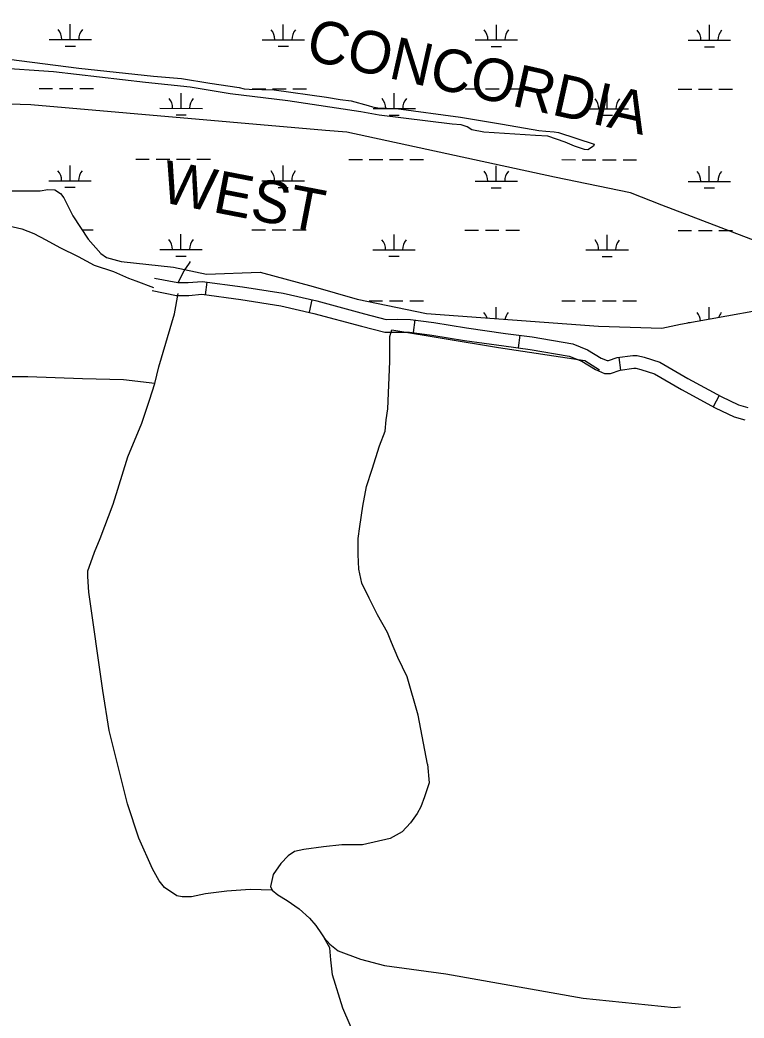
# Model space of a CAD drawing. Extents: x 3148686 to 3186545, y 916144 to 941516.
# Drawn here: x 3162503 to 3164209, y 922106 to 924457 of the extents above; entities that cross this region are included whole.
import ezdxf

# ---------------------------------------------------------------- set-up
doc = ezdxf.new("R2010")
doc.units = 0
for name, color, linetype in [('V-ROAD-CNTR', 7, 'Continuous'), ('V-SITE-VEGE', 7, 'Continuous'), ('V-TOPO-BNDY', 7, 'Continuous'), ('V-TOPO-GNAM-IDEN', 7, 'Continuous'), ('V-TOPO-SHOR', 7, 'Continuous'), ('V-WETL-SWMP', 7, 'Continuous')]:
    doc.layers.add(name, color=color, linetype=linetype)

msp = doc.modelspace()

# ---------------------------------------------------------------- linework, layer by layer
at = {"layer": 'V-ROAD-CNTR'}
for p, q in [((3162943.3, 923839.6), (3162939.3, 923809.8)), ((3163191, 923797.8), (3163184.3, 923768.5)), ((3163433.5, 923750.3), (3163429.5, 923720.5)), ((3163680.8, 923714.5), (3163676.9, 923684.7)), ((3163914, 923662.2), (3163918.2, 923632.5)), ((3164150.3, 923572.5), (3164135.9, 923546.1))]:
    msp.add_line(p, q, dxfattribs=at)
for points in [[(3162820.5, 923849.1), (3162874.9, 923838.4), (3162899.8, 923838.3), (3162932.9, 923840.9), (3163027.9, 923828.4), (3163123.6, 923813.2), (3163202.8, 923795.1), (3163315.3, 923764.9), (3163366.3, 923751.8), (3163393.5, 923751.9), (3163423, 923751.7), (3163478.3, 923744.2), (3163555.2, 923731.5), (3163646.9, 923718.8), (3163709.6, 923710.8), (3163805.5, 923694.3), (3163840.5, 923680.3), (3163872.8, 923660.1), (3163886.4, 923654.6), (3163889.4, 923654.5), (3163910.4, 923661.7), (3163946.9, 923666.9), (3163957.5, 923667), (3163973.9, 923662.8), (3164010.7, 923651.2), (3164076.8, 923612.6), (3164154.9, 923569.9), (3164196.2, 923550.5), (3164218.1, 923544)], [(3162814.7, 923819.7), (3162871.9, 923808.4), (3162901, 923808.3), (3162932.1, 923810.8), (3163023.6, 923798.7), (3163117.9, 923783.7), (3163195.6, 923765.9), (3163307.7, 923735.9), (3163362.5, 923721.8), (3163393.4, 923721.9), (3163420.8, 923721.7), (3163473.8, 923714.5), (3163550.7, 923701.8), (3163643, 923689.1), (3163705.2, 923681.1), (3163797.3, 923665.3), (3163826.9, 923653.4), (3163859, 923633.3), (3163880.3, 923624.6), (3163894.2, 923624.5), (3163917.4, 923632.4), (3163949.2, 923636.9), (3163953.9, 923637), (3163965.7, 923633.9), (3163998.4, 923623.6), (3164062, 923586.4), (3164141.3, 923543.2), (3164185.5, 923522.4), (3164210.6, 923514.9)]]:
    msp.add_lwpolyline(points, dxfattribs=at)
at = {"layer": 'V-SITE-VEGE'}
msp.add_lwpolyline([(3162312.2, 924054.6), (3162551.2, 924054.6), (3162568.8, 924057.6), (3162585.6, 924056.8), (3162599.1, 924048.1), (3162606.5, 924038.1), (3162627.8, 923995.3), (3162664.2, 923940.9), (3162693.8, 923906.7), (3162707, 923897.8), (3162741.6, 923887.8), (3162864.8, 923875.1), (3162942.8, 923858.1), (3163068.9, 923862.7), (3163193.9, 923829.3), (3163298, 923799), (3163460.7, 923765.3), (3163866.1, 923735.8), (3164015.6, 923731), (3164059.7, 923740.2), (3164347.3, 923792.4)], dxfattribs=at)
at = {"layer": 'V-TOPO-BNDY'}
msp.add_lwpolyline([(3165259.9, 923662.7), (3164600.9, 923797.2), (3164015.7, 924021.2), (3163941.6, 924049.9), (3163762.7, 924086.7), (3163273.2, 924192.5), (3163223.3, 924196.8), (3162529.1, 924257.1), (3162126.3, 924269.4), (3161732.9, 924281.4), (3160847.8, 924177.7), (3160641.8, 924139.1)], dxfattribs=at)
at = {"layer": 'V-TOPO-SHOR'}
for points in [[(3162477.3, 924364.6), (3162642.3, 924343.3), (3162818.3, 924325), (3162883.5, 924319.4), (3162950.3, 924307.9), (3163019.6, 924297.9), (3163031.3, 924295), (3163043.2, 924294), (3163102.4, 924292.6), (3163225.8, 924275.1), (3163257.9, 924269.6)], [(3163257.9, 924269.6), (3163283.3, 924266.3), (3163323.8, 924255.8), (3163334, 924252.5), (3163346.5, 924250.1), (3163389.2, 924248.7), (3163541, 924228.2), (3163640.2, 924212), (3163725.9, 924196.9), (3163742.5, 924194.9), (3163761.8, 924193.4), (3163772.1, 924192.3), (3163855.8, 924164.6), (3163854.6, 924159.7), (3163840.8, 924151.2), (3163833.1, 924152.1), (3163809.6, 924159.7), (3163787.5, 924169.3), (3163747.2, 924183.7), (3163718.1, 924184.9), (3163595.7, 924193.1), (3163567.9, 924198.3), (3163556.7, 924205.3), (3163542.4, 924209.8), (3163521.5, 924211.8), (3163349.4, 924233.2), (3163306.7, 924240.4), (3163134.2, 924266.7), (3162998.2, 924283.3), (3162904.5, 924298.5), (3162798.9, 924309.9), (3162582.4, 924334.7), (3162443.9, 924344.7)], [(3162470.3, 923974), (3162507.5, 923965.2), (3162535.9, 923954.2), (3162564.3, 923938.9), (3162597.1, 923921.4), (3162640.8, 923899.5), (3162677.9, 923879.8), (3162723.8, 923864.4), (3162758.8, 923849.1), (3162776.2, 923842.5), (3162817.8, 923827.1)], [(3162876.8, 923840.2), (3162890, 923866.4), (3162903.1, 923883.9), (3162905.3, 923888.3)], [(3163097.8, 922406.9), (3163045.3, 922409.1), (3162990.6, 922404.8), (3162940.3, 922398.3), (3162907.5, 922391.8), (3162885.7, 922391.8), (3162872.6, 922394), (3162844.2, 922413.7), (3162831.1, 922429), (3162815.8, 922457.4), (3162783.1, 922529.6), (3162756.9, 922610.5), (3162713.4, 922783.3), (3162698.2, 922877.3), (3162665.6, 923109.1), (3162663.5, 923146.3), (3162663.5, 923159.4), (3162670.1, 923179.1), (3162678.8, 923203.1), (3162692, 923235.9), (3162722.7, 923316.7), (3162733.6, 923351.7), (3162757.8, 923428.2), (3162790.6, 923506.9), (3162808.2, 923561.5), (3162821.4, 923600.9), (3162830.1, 923640.2), (3162867.4, 923764.8), (3162876.2, 923812.9)], [(3163463.2, 922703.8), (3163441.4, 922819.7), (3163415.3, 922909.4), (3163393.5, 922955.3), (3163378.2, 922990.3), (3163369.5, 923014.4), (3163345.5, 923055.9), (3163325.9, 923095.3), (3163308.4, 923130.3), (3163301.9, 923163.1), (3163299.7, 923198.1), (3163299.8, 923235.2), (3163304.2, 923263.7), (3163310.8, 923311.8), (3163319.6, 923357.7), (3163332.7, 923399.2), (3163350.3, 923453.8), (3163363.4, 923488.8), (3163365.7, 923515), (3163370.1, 923541.3), (3163374.5, 923652.8), (3163374.6, 923700.8), (3163374.6, 923711.8), (3163379, 923727.1), (3163630.4, 923685.3), (3163833.7, 923654.5), (3163868.6, 923632.6)], [(3162821.4, 923600.9), (3162747, 923609.7), (3162650.8, 923612), (3162521.9, 923616.5), (3162414.7, 923616.6)], [(3163463.2, 922703.8), (3163467.5, 922660.1), (3163456.5, 922627.3), (3163447.8, 922603.3), (3163439, 922588), (3163423.7, 922566.1), (3163404, 922544.3), (3163375.5, 922529), (3163309.9, 922513.8), (3163261.8, 922513.8), (3163218.1, 922509.5), (3163172.2, 922503), (3163150.3, 922498.6), (3163135, 922487.7), (3163117.5, 922470.2), (3163100, 922444), (3163093.4, 922415.6), (3163097.8, 922406.9), (3163110.9, 922395.9), (3163132.7, 922382.8), (3163161.1, 922363.1), (3163185.1, 922341.2), (3163200.4, 922323.7), (3163213.5, 922304), (3163220.1, 922295.2), (3163233.2, 922279.9), (3163252.8, 922264.6), (3163305.3, 922244.9), (3163362.1, 922229.5), (3163506.4, 922209.7), (3163829.9, 922152.5), (3164044.1, 922130.4), (3164059.4, 922132.6)], [(3163316, 922008.7), (3163263.6, 922129), (3163239.7, 922207.8), (3163235.3, 922242.7), (3163233.2, 922271.2), (3163220.1, 922295.2)]]:
    msp.add_lwpolyline(points, dxfattribs=at)
at = {"layer": 'V-WETL-SWMP'}
for p, q in [((3162621.8, 924411.1), (3162621.8, 924447.1)), ((3163123.7, 924410.6), (3163123.7, 924446.6)), ((3163625.6, 924410), (3163625.6, 924446)), ((3164127.5, 924409.5), (3164127.6, 924445.5)), ((3162571.8, 924411.2), (3162671.8, 924411.1)), ((3163073.7, 924410.6), (3163173.7, 924410.5)), ((3163575.6, 924410.1), (3163675.6, 924410)), ((3164077.5, 924409.6), (3164177.5, 924409.5)), ((3162609.8, 924395.7), (3162633.8, 924395.7)), ((3163111.7, 924395.2), (3163135.7, 924395.1)), ((3163613.6, 924394.6), (3163637.6, 924394.6)), ((3164115.5, 924394.1), (3164139.5, 924394.1)), ((3162548.3, 924295.8), (3162580.3, 924295.7)), ((3162596.3, 924295.7), (3162628.3, 924295.7)), ((3162644.3, 924295.6), (3162676.3, 924295.6)), ((3162883.1, 924249), (3162883.1, 924285)), ((3163050.2, 924295.2), (3163082.2, 924295.2)), ((3163098.2, 924295.2), (3163130.2, 924295.1)), ((3163146.2, 924295.1), (3163178.2, 924295.1)), ((3163385, 924248.4), (3163385, 924284.4)), ((3163552.1, 924294.7), (3163584.1, 924294.7)), ((3163600.1, 924294.6), (3163632.1, 924294.6)), ((3163648.1, 924294.6), (3163680.1, 924294.6)), ((3163886.9, 924247.9), (3163886.9, 924283.9)), ((3164054, 924294.2), (3164086, 924294.1)), ((3164102, 924294.1), (3164134, 924294.1)), ((3164150, 924294.1), (3164182, 924294)), ((3162833.1, 924249), (3162933.1, 924248.9)), ((3162871, 924233.5), (3162895, 924233.5)), ((3163335, 924248.5), (3163435, 924248.4)), ((3163372.9, 924233), (3163396.9, 924233)), ((3163836.9, 924248), (3163936.9, 924247.9)), ((3163874.9, 924232.5), (3163898.9, 924232.5)), ((3162621.4, 924078.4), (3162621.5, 924114.4)), ((3162776.1, 924129), (3162808.1, 924129)), ((3162824.1, 924129), (3162856.1, 924128.9)), ((3162872.1, 924128.9), (3162904.1, 924128.9)), ((3162920.1, 924128.9), (3162952.1, 924128.8)), ((3163123.3, 924077.9), (3163123.4, 924113.9)), ((3163278, 924128.5), (3163310, 924128.4)), ((3163326, 924128.4), (3163358, 924128.4)), ((3163374, 924128.4), (3163406, 924128.3)), ((3163422, 924128.3), (3163454, 924128.3)), ((3163779.9, 924128), (3163811.9, 924127.9)), ((3163827.9, 924127.9), (3163859.9, 924127.9)), ((3163875.9, 924127.9), (3163907.9, 924127.8)), ((3163923.9, 924127.8), (3163955.9, 924127.8)), ((3163625.3, 924077.4), (3163625.3, 924113.4)), ((3164127.2, 924076.8), (3164127.2, 924112.8)), ((3162571.4, 924078.5), (3162671.4, 924078.4)), ((3163073.3, 924078), (3163173.3, 924077.8)), ((3163575.3, 924077.4), (3163675.3, 924077.3)), ((3164077.2, 924076.9), (3164177.2, 924076.8)), ((3162609.4, 924063), (3162633.4, 924063)), ((3163111.3, 924062.5), (3163135.3, 924062.5)), ((3163613.2, 924062), (3163637.2, 924061.9)), ((3164115.1, 924061.4), (3164139.1, 924061.4)), ((3162649.5, 923963), (3162675.9, 923962.9)), ((3162882.7, 923916.3), (3162882.7, 923952.3)), ((3163049.8, 923962.5), (3163081.8, 923962.5)), ((3163097.8, 923962.5), (3163129.8, 923962.5)), ((3163145.8, 923962.4), (3163177.8, 923962.4)), ((3163384.6, 923915.8), (3163384.7, 923951.8)), ((3163551.7, 923962), (3163583.7, 923962)), ((3163599.7, 923962), (3163631.7, 923961.9)), ((3163647.7, 923961.9), (3163679.7, 923961.9)), ((3163886.5, 923915.2), (3163886.6, 923951.2)), ((3164053.6, 923961.5), (3164085.6, 923961.5)), ((3164101.6, 923961.4), (3164133.6, 923961.4)), ((3164149.6, 923961.4), (3164181.6, 923961.4)), ((3162832.7, 923916.3), (3162932.7, 923916.2)), ((3163334.6, 923915.8), (3163434.6, 923915.7)), ((3163836.5, 923915.3), (3163936.5, 923915.2)), ((3162870.7, 923900.9), (3162894.7, 923900.8)), ((3163372.6, 923900.3), (3163396.6, 923900.3)), ((3163874.5, 923899.8), (3163898.5, 923899.8)), ((3163325.6, 923795.8), (3163357.6, 923795.7)), ((3163373.6, 923795.7), (3163405.6, 923795.7)), ((3163421.6, 923795.7), (3163453.6, 923795.6)), ((3163779.5, 923795.3), (3163811.5, 923795.2)), ((3163827.5, 923795.2), (3163859.5, 923795.2)), ((3163875.5, 923795.2), (3163907.5, 923795.1)), ((3163923.5, 923795.1), (3163955.5, 923795.1)), ((3163624.9, 923753.4), (3163624.9, 923780.7)), ((3164126.8, 923752.4), (3164126.9, 923780.2)), ((3164076.8, 923744.2), (3164081.8, 923744.2))]:
    msp.add_line(p, q, dxfattribs=at)
for points in [[(3162312.2, 924054.6), (3162551.2, 924054.6)], [(3162551.2, 924054.6), (3162568.8, 924057.6), (3162585.6, 924056.8), (3162599.1, 924048.1), (3162606.5, 924038.1), (3162627.8, 923995.3), (3162664.2, 923940.9), (3162693.8, 923906.7), (3162707, 923897.8), (3162741.6, 923887.8), (3162864.8, 923875.1), (3162942.8, 923858.1), (3163068.9, 923862.7), (3163193.9, 923829.3), (3163298, 923799), (3163460.7, 923765.3), (3163866.1, 923735.8), (3164015.6, 923731), (3164059.7, 923740.2), (3164347.3, 923792.4)]]:
    msp.add_lwpolyline(points, dxfattribs=at)
for centre, start, end in [((3162566.5, 924411.6), 359.1678, 40.7115), ((3162677, 924411.5), 139.1678, 180.7115), ((3163068.5, 924411.1), 359.1678, 40.7115), ((3163178.9, 924411), 139.1678, 180.7115), ((3163570.4, 924410.6), 359.1678, 40.7115), ((3163680.8, 924410.5), 139.1678, 180.7115), ((3164072.3, 924410.1), 359.1678, 40.7115), ((3164182.8, 924409.9), 139.1678, 180.7115), ((3162827.8, 924249.5), 359.1678, 40.7115), ((3162938.3, 924249.4), 139.1678, 180.7115), ((3163329.7, 924249), 359.1678, 40.7115), ((3163440.2, 924248.9), 139.1678, 180.7115), ((3163831.6, 924248.4), 359.1678, 40.7115), ((3163942.1, 924248.3), 139.1678, 180.7115), ((3162566.2, 924079), 359.1678, 40.7115), ((3162676.7, 924078.8), 139.1678, 180.7115), ((3163068.1, 924078.4), 359.1678, 40.7115), ((3163178.6, 924078.3), 139.1678, 180.7115), ((3163570, 924077.9), 359.1678, 40.7115), ((3163680.5, 924077.8), 139.1678, 180.7115), ((3164071.9, 924077.4), 359.1678, 40.7115), ((3164182.4, 924077.3), 139.1678, 180.7115), ((3162827.5, 923916.8), 359.1678, 40.7115), ((3162937.9, 923916.7), 139.1678, 180.7115), ((3163329.4, 923916.3), 359.1678, 40.7115), ((3163439.9, 923916.2), 139.1678, 180.7115), ((3163831.3, 923915.8), 359.1678, 40.7115), ((3163941.8, 923915.7), 139.1678, 180.7115), ((3163569.7, 923745.2), 15.966, 40.7115), ((3163680.1, 923745.1), 139.1678, 168.9547), ((3164071.6, 923744.7), 6.5515, 40.7115), ((3164182.1, 923744.6), 139.1678, 160.4166)]:
    msp.add_arc(centre, 35.2, start, end, dxfattribs=at)

# ---------------------------------------------------------------- texts
at = {"layer": 'V-TOPO-GNAM-IDEN'}
for s, rotation, p in [('CONCORDIA', 347.3541, (3163173.2, 924364.8)), ('WEST', 349.0619, (3162830.8, 924029.1))]:
    msp.add_text(s, height=100, rotation=rotation, dxfattribs=at).set_placement(p)

doc.saveas('drawing.dxf')
